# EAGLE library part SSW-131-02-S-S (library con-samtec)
THROUGH-HOLE .025" SQ POST SOCKET Source: Samtec SSW.pdf
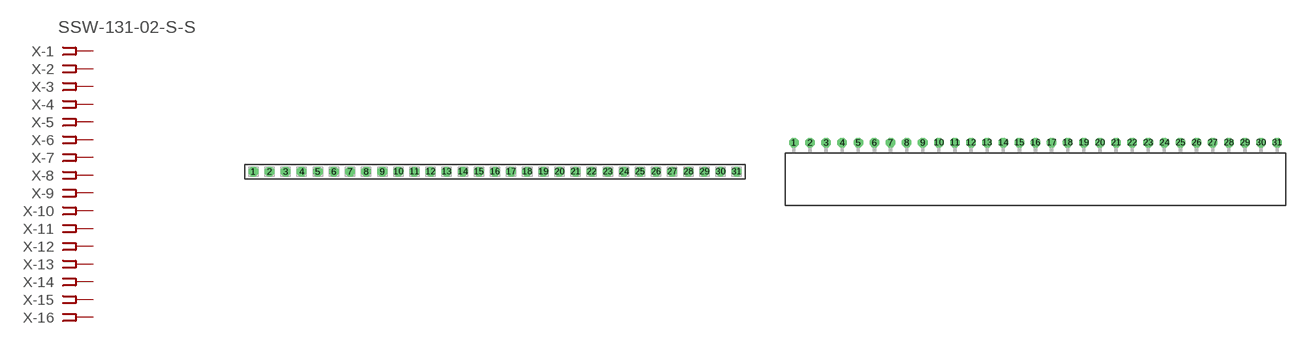
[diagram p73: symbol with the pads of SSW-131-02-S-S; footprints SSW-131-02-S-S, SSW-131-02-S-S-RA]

Designator prefix X; gates -1=FPINV -2=FPIN -3=FPIN -4=FPIN -5=FPIN -6=FPIN -7=FPIN -8=FPIN -9=FPIN -10=FPIN -11=FPIN -12=FPIN -13=FPIN -14=FPIN -15=FPIN -16=FPIN -17=FPIN -18=FPIN -19=FPIN -20=FPIN -21=FPIN -22=FPIN -23=FPIN -24=FPIN -25=FPIN -26=FPIN -27=FPIN -28=FPIN -29=FPIN -30=FPIN -31=FPIN

## SSW-131-02-S-S (MPN: SSW-131-02-S-S; OC_FARNELL: unknown; OC_NEWARK: 11P9823)  [SSW-131-02-S-S]
1  -1:1  pas
2  -2:1  pas
3  -3:1  pas
4  -4:1  pas
5  -5:1  pas
6  -6:1  pas
7  -7:1  pas
8  -8:1  pas
9  -9:1  pas
10  -10:1  pas
11  -11:1  pas
12  -12:1  pas
13  -13:1  pas
14  -14:1  pas
15  -15:1  pas
16  -16:1  pas
17  -17:1  pas
18  -18:1  pas
19  -19:1  pas
20  -20:1  pas
21  -21:1  pas
22  -22:1  pas
23  -23:1  pas
24  -24:1  pas
25  -25:1  pas
26  -26:1  pas
27  -27:1  pas
28  -28:1  pas
29  -29:1  pas
30  -30:1  pas
31  -31:1  pas

## SSW-131-02-S-S-RA (OC_FARNELL: unknown; OC_NEWARK: unknown)  [SSW-131-02-S-S-RA]
Pads as for SSW-131-02-S-S

## Footprint SSW-131-02-S-S (pad centres in mm)
THROUGH-HOLE .025" SQ POST SOCKET Source: Samtec SSW.pdf
drill 1 pad 1.5 octagon: 1 -60.96,0; 2 -58.42,0; 3 -55.88,0; 4 -53.34,0; 5 -50.8,0; 6 -48.26,0; 7 -45.72,0; 8 -43.18,0; 9 -40.64,0; 10 -38.1,0; 11 -35.56,0; 12 -33.02,0; 13 -30.48,0; 14 -27.94,0; 15 -25.4,0; 16 -22.86,0; 17 -20.32,0; 18 -17.78,0; 19 -15.24,0; 20 -12.7,0; 21 -10.16,0; 22 -7.62,0; 23 -5.08,0; 24 -2.54,0; 25 0,0; 26 2.54,0; 27 5.08,0; 28 7.62,0; 29 10.16,0; 30 12.7,0; 31 15.24,0

## Footprint SSW-131-02-S-S-RA (pad centres in mm)
THROUGH-HOLE .025" SQ POST SOCKET Source: Samtec SSW.pdf
drill 1 pad 1.5 octagon: 1 -38.1,1.524; 2 -35.56,1.524; 3 -33.02,1.524; 4 -30.48,1.524; 5 -27.94,1.524; 6 -25.4,1.524; 7 -22.86,1.524; 8 -20.32,1.524; 9 -17.78,1.524; 10 -15.24,1.524; 11 -12.7,1.524; 12 -10.16,1.524; 13 -7.62,1.524; 14 -5.08,1.524; 15 -2.54,1.524; 16 0,1.524; 17 2.54,1.524; 18 5.08,1.524; 19 7.62,1.524; 20 10.16,1.524; 21 12.7,1.524; 22 15.24,1.524; 23 17.78,1.524; 24 20.32,1.524; 25 22.86,1.524; 26 25.4,1.524; 27 27.94,1.524; 28 30.48,1.524; 29 33.02,1.524; 30 35.56,1.524; 31 38.1,1.524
